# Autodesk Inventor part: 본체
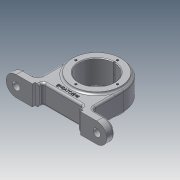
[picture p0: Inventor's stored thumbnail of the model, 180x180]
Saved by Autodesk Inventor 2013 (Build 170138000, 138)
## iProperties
Created: 2019-05
Part Number: 본체
Material: 알루미늄 6061
Document SubType Name: Modeling
Designer: a
Density: 2.71 g/cm^3
Mass: 457.66 g
Surface Area: 318.891 cm^2
Volume: 168.878 cm^3
Author: a
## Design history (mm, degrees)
sketch "스케치1"
  geometry: C1 r 40 at (0, 0); 1 further point
  constraints: 1 centre point, 1 coincident
  dimensions: "d0" = 80 diameter of C1
extrude "돌출1" new body sketch "스케치1" stored distance "d1" = 30; taper "d2" = 0 deg
sketch "스케치2"
  geometry: C1 r 40 at (0, 0) reference; C2 r 36 at (0, 0)
  constraints: 1 centre point, 1 coincident
  dimensions: "d3" = 72 diameter of C2
extrude "돌출2" join sketch "스케치2" distance "d4" = 3; taper "d5" = 0 deg
sketch "스케치3"
  geometry: C1 r 36 at (0, 0) reference; C2 r 26 at (0, 0)
  constraints: 1 centre point, 1 coincident
  dimensions: "d6" = 52 diameter of C2
extrude "돌출3" cut sketch "스케치3" stored distance "d7" = 3; taper "d8" = 0 deg
sketch "스케치4"
  geometry: L1 (0, 0)-(0, 31); C1 r 36 at (0, 0) reference; 1 further point
  constraints: 2 end point, 1 coincident, 1 vertical
  dimensions: "d9" = 31 distance of L1.start L1.end
hole "구멍1" sketch "스케치4" at (0, 31) diameter "d10" = 3.242; stored, may be unused: countersink angle "d14" = 90 deg, drill point angle "d16" = 118 deg; dims "d11" = 6, "d12" = 4, "d13" = 2, "d15" = 8
node "작업 평면1"
sketch "스케치5"
  geometry: 2 further points
  constraints: 1 coincident
hole "구멍2" sketch "스케치5" at (0, 0) diameter "d23" = 4.917; stored, may be unused: countersink angle "d27" = 90 deg, drill point angle "d29" = 118 deg; dims "d24" = 8, "d25" = 7, "d26" = 1, "d28" = 10
sketch "스케치6"
  geometry: C1 r 1 at (0, 0); 1 further point
  constraints: 1 centre point, 1 coincident
  dimensions: "d30" = 2 diameter of C1
extrude "돌출4" cut sketch "스케치6" stored distance "d31" = 3; taper "d32" = 0 deg
sketch "스케치7"
  geometry: L1 (2.458, 39)-(3.5, 39) reference; L2 (3.5, 39)-(3.5, 39.847) reference; L3 (-3.5, 39.847)-(-3.5, 39) reference; L4 (-3.5, 39)-(-2.458, 39) reference; L5 (-2.458, 39)-(-2.458, 29) reference; L6 (-2.458, 29)-(-1, 28.124) reference; L7 (-1, 28.124)-(-1, 25.981) reference; L8 (1, 25.981)-(1, 28.124) reference; L9 (1, 28.124)-(2.458, 29) reference; L10 (2.458, 29)-(2.458, 39) reference; L11 (-40, 0)-(-40, -60); L12 (-40, -60)-(40, -60); L13 (40, -60)-(40, 0); A1 r 40 centre (0, 0) between (-3.5, 39.847) and (3.5, 39.847) reference; A2 r 26 centre (0, 0) between (-1, 25.981) and (1, 25.981) reference; A3 r 40 centre (0, 0) between (-40, 0) and (40, 0); 1 further point
  constraints: 6 end point, 4 point on circle, 2 tangent, 1 centre point, 1 parallel, 1 perpendicular
  dimensions: "d33" = 60 distance of L11.start L11.end; "d34" = 80 distance of L11.end L12.end; "d35" = 60 distance of L12.end L13.end
extrude "돌출5" join sketch "스케치7" stored distance "d36" = 30; taper "d37" = 0 deg
sketch "스케치8"
  geometry: L1 (-40, -60)-(40, -60) reference; L2 (-36, -60)-(-36, -56); L3 (-36, -56)-(-30, -56); L4 (-30, -56)-(-30, -50); L5 (-30, -50)-(30, -50); L6 (30, -50)-(30, -56); L7 (30, -56)-(36, -56); L8 (36, -56)-(36, -60); L9 (-36, -60)-(36, -60); C1 r 36 at (0, 0) reference
  constraints: 16 end point, 4 perpendicular, 2 parallel, 2 point on line, 1 collinear
  dimensions: "d38" = 4 distance of L2.start L2.end; "d39" = 6 distance of L2.end L3.end; "d40" = 6 distance of L3.end L4.end; "d41" = 60 distance of L4.end L5.end; "d42" = 6 distance of L5.end L6.end; "d43" = 6 distance of L6.end L7.end; "d44" = 4 distance of L7.end L8.end; "d45" = 36 horizontal distance of L2.start C1.centre
extrude "돌출6" cut sketch "스케치8" stored distance "d46" = 30; taper "d47" = 0 deg
sketch "스케치9" dims "d50" = 30, "d51" = 30
  geometry: L1 (76, 30)-(76, 0) reference; L2 (80, 0)-(76, 0) reference; L3 (80, 0)-(80, 30) reference; L4 (76, 30)-(80, 30) reference; L5 (-20, 30)-(0, 30); L6 (0, 30)-(0, 0); L7 (0, 0)-(-20, 0); L8 (-20, 0)-(-20, 30); L9 (80, 30)-(100, 30); L10 (100, 30)-(100, 0); L11 (100, 0)-(80, 0); L12 (80, 0)-(80, 30); 5 further points
  constraints: 16 end point, 4 parallel, 2 coincident, 2 horizontal, 2 horizontal alignment, 2 perpendicular, 2 vertical alignment, 4 other
  dimensions: "d48" = 60 distance of point (-20, 15) point (40, 15); "d49" = 60 distance of point (100, 15) point (40, 15); "d52" = 30 distance of L9.end L10.end; "d53" = 30 distance of L7.end L5.start
extrude "돌출7" join sketch "스케치9" distance "d54" = 12; taper "d55" = 0 deg
sketch "스케치10"
  geometry: C1 r 9 at (-20, -15); C2 r 9 at (100, -15); A1 r 15 centre (-20, -15) between (-20, 0) and (-20, -30) reference; A2 r 15 centre (100, -15) between (100, -30) and (100, 0) reference; 1 further point
  constraints: 2 centre point, 2 coincident
  dimensions: "d56" = 18 diameter of C1; "d57" = 18 diameter of C2
extrude "돌출8" join sketch "스케치10" distance "d58" = 3; taper "d59" = 0 deg
sketch "스케치11"
  geometry: C1 r 9 at (0, 0) reference; C2 r 9 at (120, 0) reference; 3 further points
  constraints: 2 coincident
hole "구멍3" sketch "스케치11" at (0, 0), (120, 0) diameter "d60" = 11; stored, may be unused: countersink angle "d64" = 90 deg, drill point angle "d66" = 118 deg; dims "d61" = 8, "d62" = 4, "d63" = 2, "d65" = 10
fillet "모깎기3" dims "d67" = 6
chamfer "모따기1" distance "d70" = 1; stored, may be unused: second distance "d71" = 2, angle "d72" = 45 deg
fillet "모깎기6" dims "d73" = 3
fillet "모깎기7" dims "d74" = 3
sketch "스케치12"
  geometry: L1 (27, -47)-(-27, -47) reference; L2 (-27, -50)-(27, -50) reference; 2 further points
  constraints: 1 midpoint, 1 vertical alignment, 1 other
  dimensions: "d75" = 7 distance from line of L2 point (0, -43)
feature "엠보싱1" sketch "스케치12" dims "d76" = 0.5, "d77" = 0
sketch "스케치13"
  geometry: C1 r 1.5 at (0, 26); 1 further point
  constraints: 1 centre point, 1 vertical alignment, 1 other
  dimensions: "d78" = 3 diameter of C1
extrude "돌출9" cut sketch "스케치13" stored distance "d79" = 3; taper "d80" = 0 deg
fillet "모깎기8" dims "d81" = 3
fillet "모깎기9" dims "d82" = 3
node "솔리드1"
mirror "대칭1"
pattern_circular "원형 패턴1" dims angle "d18" = 360 deg
mirror "대칭2"
node "투영된 루프1"
node "절단 모서리 투영1"
